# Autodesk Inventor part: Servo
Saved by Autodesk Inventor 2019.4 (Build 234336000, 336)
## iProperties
Created: 2020-02
Part Number: Servo
Material: Generic
Document SubType Name: Modeling
Designer: Administrator
Density: 1 g/cm^3
Appearance: Default
Title: Servo v14
Author: Administrator
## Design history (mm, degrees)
feature "Body1"
body "Solid1"
